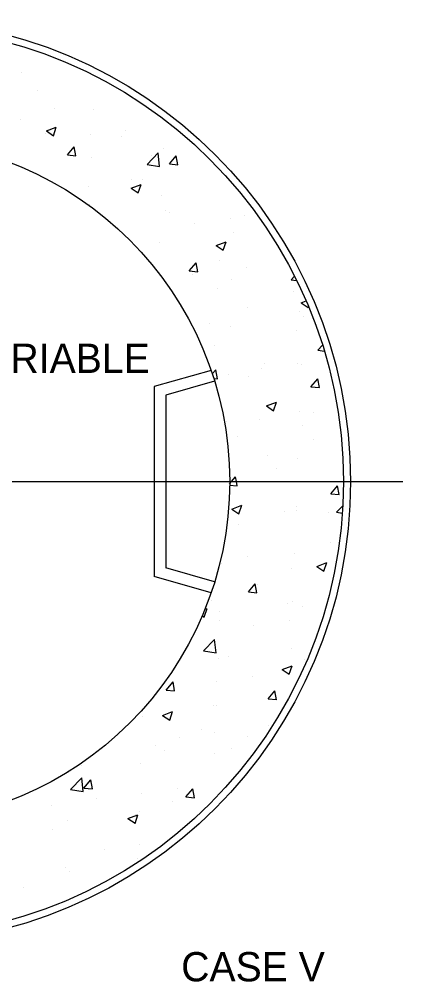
# Model space of a CAD drawing. Extents: x 6712067 to 6713867, y 1867712 to 1869162.
# Drawn here: x 6713649.4 to 6713728, y 1867919.7 to 1868116.9 of the extents above; entities that cross this region are included whole.
import ezdxf

# ---------------------------------------------------------------- set-up
doc = ezdxf.new("R2010")
doc.units = 0
doc.layers.add('Misc CnstDet(22)', color=7, linetype='Continuous')

msp = doc.modelspace()

# ---------------------------------------------------------------- linework, layer by layer
at = {"layer": 'Misc CnstDet(22)'}
for p, q in [((6713649.95, 1868105.95), (6713649.95, 1868105.95)), ((6713653.23, 1868102.29), (6713653.23, 1868102.29)), ((6713656.63, 1868098.6), (6713656.63, 1868098.6)), ((6713664.56, 1868098.31), (6713664.56, 1868098.31)), ((6713649.59, 1868096.25), (6713649.59, 1868096.25)), ((6713654.8, 1868093.49), (6713654.8, 1868093.49)), ((6713654.98, 1868093.99), (6713657.02, 1868094.78)), ((6713654.98, 1868093.99), (6713656.42, 1868093.02)), ((6713656.42, 1868093.02), (6713657.02, 1868094.77)), ((6713663.97, 1868093.21), (6713663.97, 1868093.21)), ((6713671.26, 1868094.17), (6713671.26, 1868094.17)), ((6713670.37, 1868092.83), (6713670.37, 1868092.83)), ((6713659.3, 1868089.07), (6713660.7, 1868090.74)), ((6713661.05, 1868088.92), (6713660.7, 1868090.74)), ((6713660.94, 1868089.57), (6713660.94, 1868089.57)), ((6713675.61, 1868087.12), (6713677.88, 1868089.48)), ((6713678.2, 1868086.72), (6713677.88, 1868089.48)), ((6713678.93, 1868090.47), (6713678.93, 1868090.47)), ((6713659.3, 1868089.07), (6713661.05, 1868088.92)), ((6713664.2, 1868088.6), (6713664.2, 1868088.6)), ((6713676.51, 1868088.92), (6713676.51, 1868088.92)), ((6713680.21, 1868087.24), (6713681.61, 1868088.92)), ((6713680.21, 1868087.24), (6713681.96, 1868087.08)), ((6713681.96, 1868087.08), (6713681.61, 1868088.91)), ((6713675.61, 1868087.12), (6713678.2, 1868086.72)), ((6713689.43, 1868087.05), (6713689.43, 1868087.05)), ((6713672.43, 1868084.12), (6713672.43, 1868084.12)), ((6713674.64, 1868084.12), (6713674.64, 1868084.12)), ((6713663.6, 1868082.68), (6713663.6, 1868082.68)), ((6713672.37, 1868082.26), (6713674.42, 1868083.04)), ((6713672.37, 1868082.26), (6713673.82, 1868081.28)), ((6713673.82, 1868081.28), (6713674.42, 1868083.04)), ((6713678.57, 1868080.76), (6713678.57, 1868080.76)), ((6713663.85, 1868078.9), (6713663.85, 1868078.9)), ((6713679.42, 1868077.73), (6713679.42, 1868077.73)), ((6713680.12, 1868077.36), (6713680.12, 1868077.36)), ((6713692.68, 1868076.02), (6713692.68, 1868076.02)), ((6713695.68, 1868076.7), (6713695.68, 1868076.7)), ((6713685.38, 1868075.06), (6713685.38, 1868075.06)), ((6713693.36, 1868073.24), (6713693.36, 1868073.24)), ((6713678.22, 1868071.06), (6713678.22, 1868071.06)), ((6713689.77, 1868070.52), (6713691.82, 1868071.3)), ((6713689.77, 1868070.52), (6713691.23, 1868069.55)), ((6713691.22, 1868069.55), (6713691.82, 1868071.3)), ((6713690.55, 1868067.53), (6713690.55, 1868067.53)), ((6713684.25, 1868065.31), (6713685.66, 1868066.99)), ((6713686, 1868065.16), (6713685.66, 1868066.99)), ((6713696.05, 1868065.97), (6713696.05, 1868065.97)), ((6713684.25, 1868065.31), (6713686, 1868065.16)), ((6713685.01, 1868064.52), (6713685.01, 1868064.52)), ((6713693.01, 1868063.55), (6713693.01, 1868063.55)), ((6713705.16, 1868063.49), (6713705.83, 1868064.27)), ((6713690, 1868061.8), (6713690, 1868061.8)), ((6713705.16, 1868063.49), (6713706.26, 1868063.38)), ((6713705.56, 1868061.15), (6713705.56, 1868061.15)), ((6713696.15, 1868057.89), (6713696.15, 1868057.89)), ((6713707.17, 1868058.78), (6713708.2, 1868059.18)), ((6713707.17, 1868058.78), (6713708.63, 1868057.81)), ((6713708.63, 1868057.81), (6713708.7, 1868058.03)), ((6713706.79, 1868056.9), (6713706.79, 1868056.9)), ((6713707.62, 1868055.89), (6713707.62, 1868055.89)), ((6713688.38, 1868054.48), (6713688.38, 1868054.48)), ((6713692.65, 1868053.84), (6713692.65, 1868053.84)), ((6713706.34, 1868053.06), (6713706.34, 1868053.06)), ((6713689.35, 1868050.13), (6713689.35, 1868050.13)), ((6713710.59, 1868049.07), (6713711.59, 1868050.11)), ((6713710.59, 1868049.07), (6713711.97, 1868048.86)), ((6713699.77, 1868046.33), (6713699.77, 1868046.33)), ((6713706.41, 1868046.37), (6713706.41, 1868046.37)), ((6713707.26, 1868046.18), (6713707.26, 1868046.18)), ((6713688.74, 1868044.93), (6713677.1, 1868041.6)), ((6713688.99, 1868044.21), (6713689.7, 1868045.06)), ((6713690.04, 1868043.23), (6713689.7, 1868045.06)), ((6713692.3, 1868044.14), (6713692.3, 1868044.14)), ((6713699.13, 1868045.4), (6713699.13, 1868045.4)), ((6713689.46, 1868042.72), (6713679.44, 1868039.85)), ((6713689.28, 1868043.3), (6713690.05, 1868043.23)), ((6713696.33, 1868043.74), (6713696.33, 1868043.74)), ((6713709.21, 1868041.56), (6713710.61, 1868043.23)), ((6713710.95, 1868041.41), (6713710.61, 1868043.23)), ((6713677.1, 1868041.6), (6713677.1, 1868002.69)), ((6713709.21, 1868041.56), (6713710.95, 1868041.41)), ((6713679.44, 1868039.85), (6713679.44, 1868004.46)), ((6713700.08, 1868037.64), (6713702.12, 1868038.44)), ((6713701.54, 1868036.67), (6713702.12, 1868038.42)), ((6713700.08, 1868037.64), (6713701.54, 1868036.67)), ((6713706.91, 1868036.48), (6713706.91, 1868036.48)), ((6713709.79, 1868036.32), (6713709.79, 1868036.32)), ((6713691.94, 1868034.43), (6713691.94, 1868034.43)), ((6713698.75, 1868034.87), (6713698.75, 1868034.87)), ((6713707.46, 1868033.54), (6713707.46, 1868033.54)), ((6713694.09, 1868031.44), (6713694.09, 1868031.44)), ((6713709.65, 1868030.78), (6713709.65, 1868030.78)), ((6713700.24, 1868027.52), (6713700.24, 1868027.52)), ((6713706.55, 1868026.78), (6713706.55, 1868026.78)), ((6713702.12, 1868024.82), (6713702.12, 1868024.82)), ((6713498.03, 1868022.15), (6713728.02, 1868022.15)), ((6713692.55, 1868021.71), (6713692.92, 1868022.15)), ((6713692.92, 1868022.15), (6713693.75, 1868023.14)), ((6713693.93, 1868022.15), (6713693.75, 1868023.14)), ((6713694.09, 1868021.3), (6713693.93, 1868022.15)), ((6713692.55, 1868021.44), (6713694.09, 1868021.31)), ((6713713.25, 1868019.64), (6713714.65, 1868021.3)), ((6713715, 1868019.48), (6713714.65, 1868021.3)), ((6713713.25, 1868019.64), (6713715, 1868019.48)), ((6713692.99, 1868016.52), (6713695.03, 1868017.3)), ((6713692.99, 1868016.52), (6713694.44, 1868015.53)), ((6713694.44, 1868015.53), (6713695.03, 1868017.3)), ((6713706.19, 1868017.08), (6713706.19, 1868017.08)), ((6713714.46, 1868015.85), (6713715.74, 1868017.19)), ((6713703.85, 1868015.97), (6713703.85, 1868015.97)), ((6713706.25, 1868016.14), (6713706.25, 1868016.14)), ((6713712.86, 1868015.75), (6713712.86, 1868015.75)), ((6713714.46, 1868015.85), (6713715.65, 1868015.67)), ((6713694.45, 1868013.33), (6713694.45, 1868013.33)), ((6713713.24, 1868009.73), (6713713.24, 1868009.73)), ((6713696.24, 1868006.82), (6713696.24, 1868006.82)), ((6713705.84, 1868007.37), (6713705.84, 1868007.37)), ((6713689.46, 1868001.59), (6713679.44, 1868004.46)), ((6713690.87, 1868005.32), (6713690.87, 1868005.32)), ((6713710.38, 1868004.78), (6713712.43, 1868005.56)), ((6713710.38, 1868004.78), (6713711.84, 1868003.8)), ((6713711.84, 1868003.79), (6713712.43, 1868005.56)), ((6713712.49, 1868005.21), (6713712.49, 1868005.21)), ((6713688.74, 1867999.36), (6713677.1, 1868002.69)), ((6713705.2, 1868004.25), (6713705.2, 1868004.25)), ((6713696.39, 1867999.53), (6713697.79, 1868001.21)), ((6713698.13, 1867999.38), (6713697.79, 1868001.21)), ((6713698.17, 1868001.07), (6713698.17, 1868001.07)), ((6713696.39, 1867999.53), (6713698.13, 1867999.38)), ((6713688.76, 1867997.81), (6713688.76, 1867997.81)), ((6713704.32, 1867997.16), (6713704.32, 1867997.16)), ((6713705.49, 1867997.67), (6713705.49, 1867997.67)), ((6713707.38, 1867996.62), (6713707.38, 1867996.62)), ((6713686.94, 1867994.68), (6713687.35, 1867994.39)), ((6713687.35, 1867994.39), (6713687.94, 1867996.16)), ((6713687.48, 1867995.99), (6713687.94, 1867996.16)), ((6713690.52, 1867995.62), (6713690.52, 1867995.62)), ((6713690.38, 1867993.7), (6713690.38, 1867993.7)), ((6713697.53, 1867992.75), (6713697.53, 1867992.75)), ((6713704.82, 1867993.71), (6713704.82, 1867993.71)), ((6713687.21, 1867987.46), (6713689.47, 1867989.82)), ((6713689.8, 1867987.06), (6713689.47, 1867989.82)), ((6713687.21, 1867987.46), (6713689.8, 1867987.06)), ((6713705.14, 1867987.96), (6713705.14, 1867987.96)), ((6713690.17, 1867985.91), (6713690.17, 1867985.91)), ((6713692.38, 1867986.25), (6713692.38, 1867986.25)), ((6713707.94, 1867985.59), (6713707.94, 1867985.59)), ((6713703.29, 1867983.64), (6713705.33, 1867984.42)), ((6713703.29, 1867983.64), (6713704.75, 1867982.66)), ((6713704.75, 1867982.66), (6713705.33, 1867984.42)), ((6713679.52, 1867979.44), (6713680.94, 1867981.11)), ((6713681.27, 1867979.29), (6713680.94, 1867981.11)), ((6713689.85, 1867981.26), (6713689.85, 1867981.26)), ((6713697.15, 1867982.21), (6713697.15, 1867982.21)), ((6713679.52, 1867979.44), (6713681.27, 1867979.29)), ((6713700.43, 1867977.61), (6713701.83, 1867979.29)), ((6713702.18, 1867977.45), (6713701.83, 1867979.29)), ((6713700.43, 1867977.61), (6713702.18, 1867977.46)), ((6713704.78, 1867978.27), (6713704.78, 1867978.27)), ((6713678.8, 1867974.24), (6713680.84, 1867975.02)), ((6713680.26, 1867973.25), (6713680.84, 1867975.02)), ((6713689.18, 1867976.3), (6713689.18, 1867976.3)), ((6713689.82, 1867976.21), (6713689.82, 1867976.21)), ((6713674.67, 1867974.02), (6713674.67, 1867974.02)), ((6713678.8, 1867974.24), (6713680.26, 1867973.26)), ((6713686.7, 1867971.36), (6713686.7, 1867971.36)), ((6713700.53, 1867972.17), (6713700.53, 1867972.17)), ((6713682.19, 1867969.76), (6713682.19, 1867969.76)), ((6713689.49, 1867970.73), (6713689.49, 1867970.73)), ((6713696.15, 1867969.91), (6713696.15, 1867969.91)), ((6713677.29, 1867968.1), (6713677.29, 1867968.1)), ((6713679.16, 1867967), (6713679.16, 1867967)), ((6713692.85, 1867967.44), (6713692.85, 1867967.44)), ((6713689.46, 1867966.5), (6713689.46, 1867966.5)), ((6713662.16, 1867964.07), (6713662.16, 1867964.07)), ((6713674.33, 1867964.32), (6713674.33, 1867964.32)), ((6713659.6, 1867962.45), (6713659.6, 1867962.45)), ((6713659.96, 1867959.07), (6713662.23, 1867961.43)), ((6713662.55, 1867958.65), (6713662.23, 1867961.43)), ((6713662.67, 1867959.34), (6713664.07, 1867961.02)), ((6713664.41, 1867959.19), (6713664.07, 1867961.02)), ((6713659.96, 1867959.07), (6713662.55, 1867958.67)), ((6713662.67, 1867959.34), (6713664.41, 1867959.19)), ((6713681.82, 1867959.23), (6713681.82, 1867959.23)), ((6713683.58, 1867957.52), (6713684.98, 1867959.19)), ((6713685.31, 1867957.36), (6713684.98, 1867959.18)), ((6713665.34, 1867957.2), (6713665.34, 1867957.2)), ((6713674.52, 1867958.26), (6713674.52, 1867958.26)), ((6713683.58, 1867957.52), (6713685.31, 1867957.36)), ((6713656.11, 1867955.84), (6713656.11, 1867955.84)), ((6713680.9, 1867956.54), (6713680.9, 1867956.54)), ((6713689.11, 1867956.81), (6713689.11, 1867956.81)), ((6713671.71, 1867953.1), (6713673.75, 1867953.88)), ((6713671.71, 1867953.1), (6713673.17, 1867952.12)), ((6713673.16, 1867952.11), (6713673.75, 1867953.88)), ((6713673.29, 1867953.87), (6713673.29, 1867953.87)), ((6713673.97, 1867954.61), (6713673.97, 1867954.61)), ((6713659.25, 1867952.76), (6713659.25, 1867952.76)), ((6713656.3, 1867950.95), (6713656.3, 1867950.95)), ((6713674.15, 1867947.73), (6713674.15, 1867947.73)), ((6713666.85, 1867946.77), (6713666.85, 1867946.77)), ((6713673.61, 1867944.92), (6713673.61, 1867944.92)), ((6713658.89, 1867943.05), (6713658.89, 1867943.05)), ((6713659.67, 1867942.3), (6713659.67, 1867942.3)), ((6713650.25, 1867939.04), (6713650.25, 1867939.04))]:
    msp.add_line(p, q, dxfattribs=at)
for radius in [94.73, 93.28, 69.96]:
    msp.add_circle((6713622.6, 1868022.15), radius, dxfattribs=at)

# ---------------------------------------------------------------- texts
for s, p in [('VARIABLE', (6713636.93, 1868044.41)), ('CASE V', (6713682.62, 1867919.74))]:
    msp.add_text(s, height=6, dxfattribs=at).set_placement(p)

doc.saveas('drawing.dxf')
